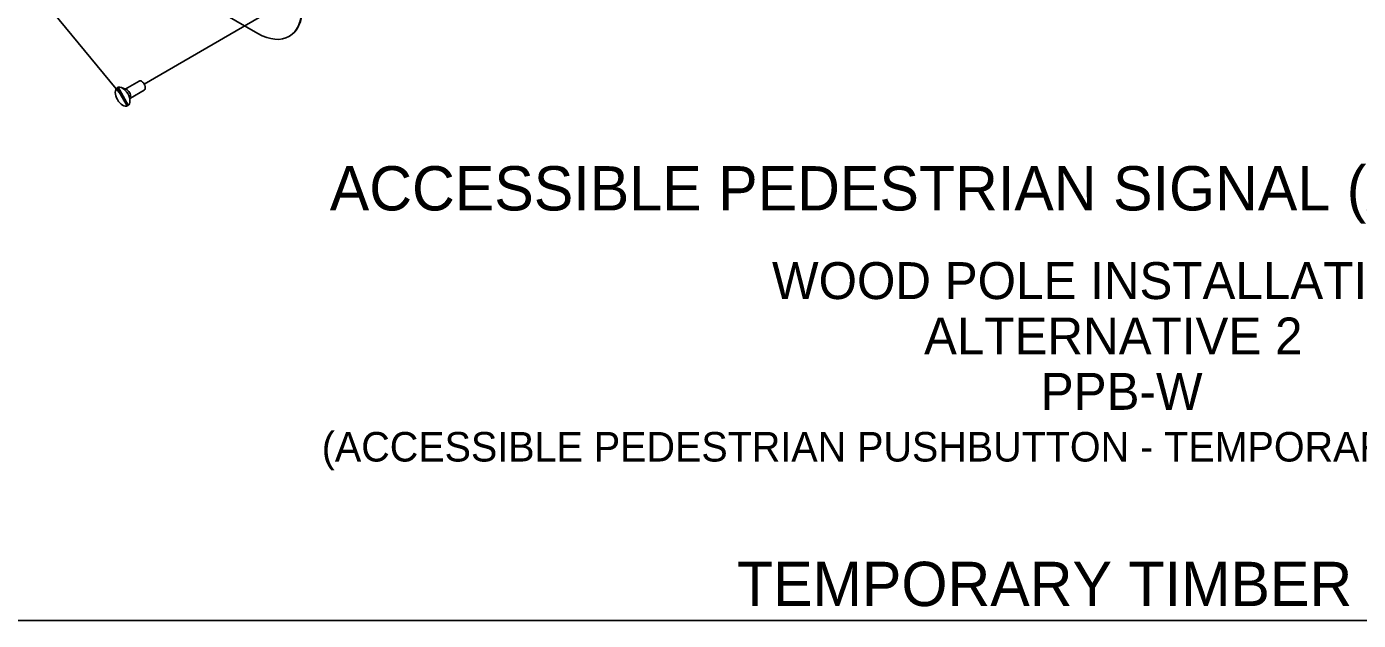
# Model space of a CAD drawing. Extents: x 99862 to 103151, y 100000 to 105076.
# Drawn here: x 100805 to 101527, y 103000 to 103321 of the extents above; entities that cross this region are included whole.
import ezdxf

# ---------------------------------------------------------------- set-up
doc = ezdxf.new("R2010")
doc.units = 0
for name, color, linetype in [('Level 1', 7, 'Continuous'), ('Level 15', 7, 'Continuous'), ('Level 16', 7, 'Continuous'), ('Level 20', 7, 'Continuous'), ('Level 40', 7, 'Continuous'), ('Level 41', 7, 'Continuous')]:
    doc.layers.add(name, color=color, linetype=linetype)

msp = doc.modelspace()

# ---------------------------------------------------------------- linework, layer by layer
at = {"layer": 'Level 1'}
msp.add_lwpolyline([(99862, 102999.5), (103151, 102999.5), (103151, 105075.5), (99862, 105075.5)], close=True, dxfattribs=at)
at = {"layer": 'Level 15'}
msp.add_line((100655.5, 103528.32), (100857.37, 103283.22), dxfattribs=at)
at = {"layer": 'Level 16'}
msp.add_line((100869.12, 103290), (100940.52, 103331.22), dxfattribs=at)
at = {"layer": 'Level 40'}
msp.add_line((100930.67, 103317.47), (100835.21, 103372.58), dxfattribs=at)
for centre, start_param in [((100930.67, 103345.03), 5.497787), ((100930.87, 103345.14), 6.283185)]:
    msp.add_ellipse(centre, major_axis=(16.88, -29.23), ratio=0.57735, start_param=start_param, end_param=7.068583, dxfattribs=at)
at = {"layer": 'Level 41'}
for p, q in [((100854.26, 103287.87), (100859.84, 103278.2)), ((100854.91, 103288.25), (100860.49, 103278.57)), ((100859.45, 103287.05), (100856.76, 103288.11)), ((100866.31, 103291.63), (100858.81, 103287.3)), ((100861.63, 103282.43), (100869.12, 103286.76))]:
    msp.add_line(p, q, dxfattribs=at)
msp.add_ellipse((100857.37, 103283.22), major_axis=(-2.81, 4.87), ratio=0.57735, dxfattribs=at)
for centre, start_param, end_param in [((100859.76, 103284.6), 0.630137, 2.511455), ((100867.72, 103289.19), 6.28318, 9.424778), ((100867.72, 103289.19), 3.141593, 3.141605)]:
    msp.add_ellipse(centre, major_axis=(1.41, -2.44), ratio=0.57735, start_param=start_param, end_param=end_param, dxfattribs=at)

# ---------------------------------------------------------------- texts
at = {"layer": 'Level 20'}
for s, height, p in [('ACCESSIBLE PEDESTRIAN SIGNAL (ASP) ASSEMBLY', 24, (100969.65, 103221.54)), ('WOOD POLE INSTALLATION', 20, (101209.31, 103173.54)), ('ALTERNATIVE 2', 20, (101291.68, 103143.54)), ('PPB-W', 20, (101354.94, 103113.54)), ('(ACCESSIBLE PEDESTRIAN PUSHBUTTON - TEMPORARY TIMBER STRAIN POLE)', 16, (100965.32, 103085.54)), ('TEMPORARY TIMBER POLE', 24, (101190.29, 103007.24))]:
    msp.add_text(s, height=height, dxfattribs=at).set_placement(p)

doc.saveas('drawing.dxf')
